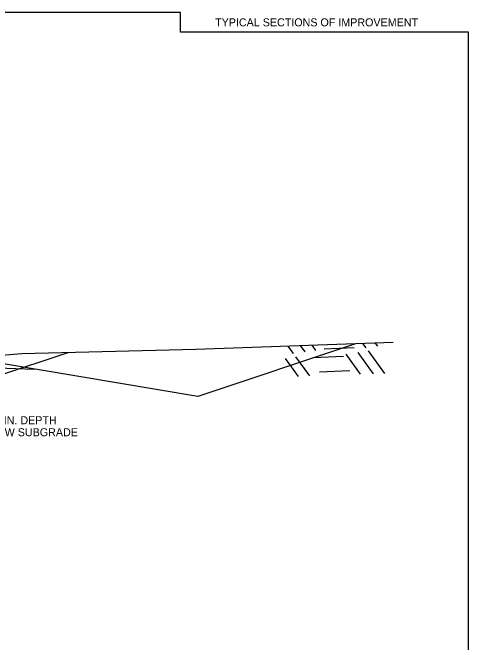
# Model space of a CAD drawing. Extents: x 1461846 to 1462006, y 1686171 to 1686805.
# Drawn here: x 1461971.75 to 1462005.89, y 1686620.82 to 1686668 of the extents above; entities that cross this region are included whole.
import ezdxf

# ---------------------------------------------------------------- set-up
doc = ezdxf.new("R2010")
doc.units = 0
for name, color, linetype in [('1', 7, 'Continuous'), ('10', 7, 'Continuous'), ('19', 7, 'Continuous'), ('R_Draft', 7, 'Continuous')]:
    doc.layers.add(name, color=color, linetype=linetype)

msp = doc.modelspace()

# ---------------------------------------------------------------- linework, layer by layer
at = {"layer": '10'}
for p, q in [((1461984.339, 1686667.999), (1461964.759, 1686667.999)), ((1461984.339, 1686666.539), (1461984.339, 1686667.999)), ((1462005.889, 1686666.539), (1461984.339, 1686666.539)), ((1462005.889, 1686568.707), (1462005.889, 1686666.539))]:
    msp.add_line(p, q, dxfattribs=at)
at = {"layer": '19'}
for p, q in [((1461997.443, 1686643.195), (1461985.621, 1686639.254)), ((1461992.781, 1686642.456), (1461992.38, 1686643.016)), ((1461993.672, 1686642.58), (1461993.323, 1686643.056)), ((1461994.463, 1686642.7), (1461994.187, 1686643.085)), ((1461998.223, 1686642.888), (1461997.985, 1686643.219)), ((1461999.114, 1686643.012), (1461998.94, 1686643.25)), ((1461985.621, 1686639.254), (1461963.621, 1686642.921)), ((1461975.9, 1686642.519), (1461968.121, 1686639.926)), ((1461997.335, 1686642.886), (1461995.076, 1686642.795)), ((1461998.775, 1686640.946), (1461997.626, 1686642.533)), ((1461999.629, 1686640.973), (1461998.417, 1686642.653)), ((1461993.168, 1686640.753), (1461992.184, 1686642.101)), ((1461994.023, 1686640.781), (1461992.975, 1686642.22)), ((1461996.527, 1686642.229), (1461994.259, 1686642.136)), ((1461997.82, 1686640.914), (1461996.734, 1686642.409)), ((1461956.082, 1686641.932), (1461973.397, 1686641.291)), ((1461997.007, 1686641.175), (1461994.749, 1686641.073))]:
    msp.add_line(p, q, dxfattribs=at)
at = {"layer": 'R_Draft'}
msp.add_lwpolyline([(1462000.252, 1686643.294), (1461985.479, 1686642.773), (1461972.442, 1686642.427), (1461966.445, 1686641.94), (1461956.315, 1686639.45), (1461938.121, 1686642.877), (1461934.871, 1686643.842), (1461929.37, 1686643.781), (1461912.792, 1686644.39), (1461910.871, 1686644.73), (1461906.121, 1686644.095), (1461890.249, 1686639.689)], dxfattribs=at)

# ---------------------------------------------------------------- texts
at = {"layer": '1'}
msp.add_text('TYPICAL SECTIONS OF IMPROVEMENT', height=0.6, dxfattribs=at).set_placement((1461986.919, 1686666.969))
at = {"layer": 'R_Draft'}
for s, p in [('18" MIN. DEPTH', (1461969.021, 1686637.165)), ('BELOW SUBGRADE', (1461969.021, 1686636.265))]:
    msp.add_text(s, height=0.6, dxfattribs=at).set_placement(p)

doc.saveas('drawing.dxf')
